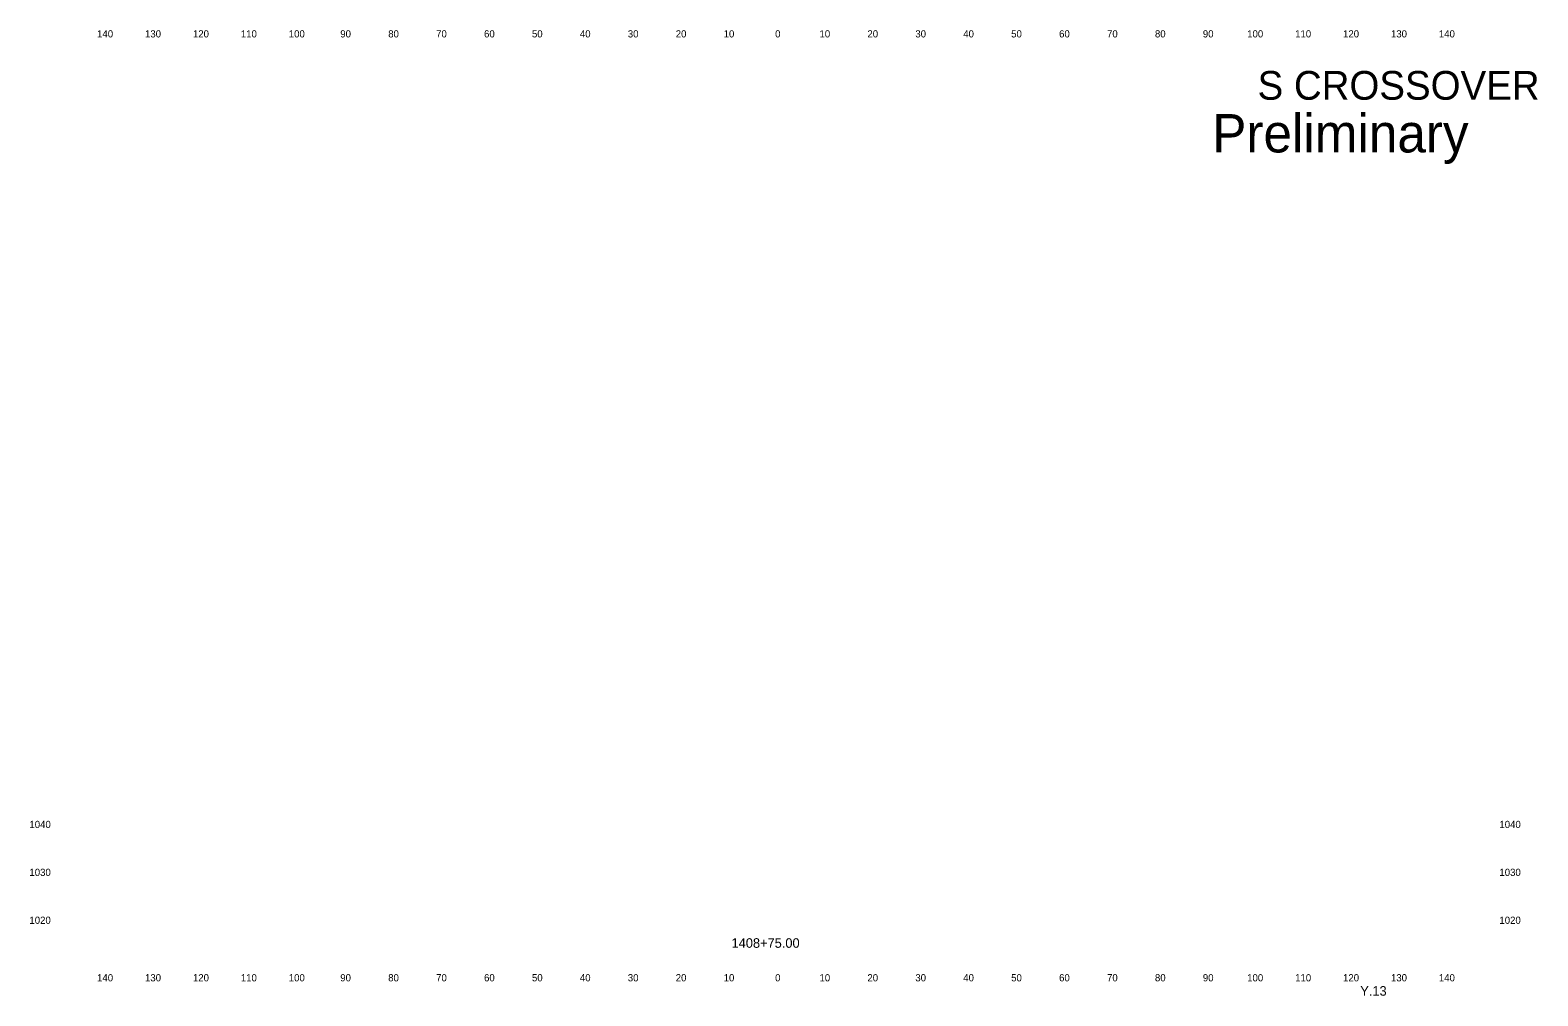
# Model space of a CAD drawing. Extents: x 10123 to 14768, y 9730 to 9950.
# Drawn here: x 14453.3 to 14767.9, y 9739 to 9940.5 of the extents above; entities that cross this region are included whole.
import ezdxf

# ---------------------------------------------------------------- set-up
doc = ezdxf.new("R2010")
doc.units = 0
for name, color, linetype in [('dsnTextCpn', 7, 'Continuous'), ('dsnTextCpnTitleSheetLocDesc', 7, 'Continuous'), ('dsnTextCpnTitleSheetPIN', 7, 'Continuous')]:
    doc.layers.add(name, color=color, linetype=linetype)

msp = doc.modelspace()

# ---------------------------------------------------------------- texts
at = {"layer": 'dsnTextCpn'}
for s, height, p in [('140', 1.5, (14467.27, 9939)), ('130', 1.5, (14477.27, 9939)), ('120', 1.5, (14487.27, 9939)), ('110', 1.5, (14497.27, 9939)), ('100', 1.5, (14507.27, 9939)), ('90', 1.5, (14518.02, 9939)), ('80', 1.5, (14528.02, 9939)), ('70', 1.5, (14538.02, 9939)), ('60', 1.5, (14548.02, 9939)), ('50', 1.5, (14558.02, 9939)), ('40', 1.5, (14568.02, 9939)), ('30', 1.5, (14578.02, 9939)), ('20', 1.5, (14588.02, 9939)), ('10', 1.5, (14598.02, 9939)), ('0', 1.5, (14608.76, 9939)), ('0', 1.5, (14608.76, 9939)), ('10', 1.5, (14618.02, 9939)), ('20', 1.5, (14628.02, 9939)), ('30', 1.5, (14638.02, 9939)), ('40', 1.5, (14648.02, 9939)), ('50', 1.5, (14658.02, 9939)), ('60', 1.5, (14668.02, 9939)), ('70', 1.5, (14678.02, 9939)), ('80', 1.5, (14688.02, 9939)), ('90', 1.5, (14698.02, 9939)), ('100', 1.5, (14707.27, 9939)), ('110', 1.5, (14717.27, 9939)), ('120', 1.5, (14727.27, 9939)), ('130', 1.5, (14737.27, 9939)), ('140', 1.5, (14747.27, 9939)), ('S CROSSOVER', 6, (14709.44, 9926)), ('1040', 1.5, (14453.15, 9774)), ('1040', 1.5, (14759.9, 9774)), ('1030', 1.5, (14453.15, 9764)), ('1030', 1.5, (14759.9, 9764)), ('1020', 1.5, (14453.15, 9754)), ('1020', 1.5, (14759.9, 9754)), ('1408+75.00', 2, (14599.67, 9749)), ('140', 1.5, (14467.27, 9742)), ('130', 1.5, (14477.27, 9742)), ('120', 1.5, (14487.27, 9742)), ('110', 1.5, (14497.27, 9742)), ('100', 1.5, (14507.27, 9742)), ('90', 1.5, (14518.02, 9742)), ('80', 1.5, (14528.02, 9742)), ('70', 1.5, (14538.02, 9742)), ('60', 1.5, (14548.02, 9742)), ('50', 1.5, (14558.02, 9742)), ('40', 1.5, (14568.02, 9742)), ('30', 1.5, (14578.02, 9742)), ('20', 1.5, (14588.02, 9742)), ('10', 1.5, (14598.02, 9742)), ('0', 1.5, (14608.76, 9742)), ('0', 1.5, (14608.76, 9742)), ('10', 1.5, (14618.02, 9742)), ('20', 1.5, (14628.02, 9742)), ('30', 1.5, (14638.02, 9742)), ('40', 1.5, (14648.02, 9742)), ('50', 1.5, (14658.02, 9742)), ('60', 1.5, (14668.02, 9742)), ('70', 1.5, (14678.02, 9742)), ('80', 1.5, (14688.02, 9742)), ('90', 1.5, (14698.02, 9742)), ('100', 1.5, (14707.27, 9742)), ('110', 1.5, (14717.27, 9742)), ('120', 1.5, (14727.27, 9742)), ('130', 1.5, (14737.27, 9742)), ('140', 1.5, (14747.27, 9742))]:
    msp.add_text(s, height=height, dxfattribs=at).set_placement(p)
at = {"layer": 'dsnTextCpnTitleSheetLocDesc'}
msp.add_text('Preliminary', height=8, dxfattribs=at).set_placement((14699.97, 9915))
at = {"layer": 'dsnTextCpnTitleSheetPIN'}
msp.add_text('Y.13', height=2, dxfattribs=at).set_placement((14730.87, 9739))

doc.saveas('drawing.dxf')
